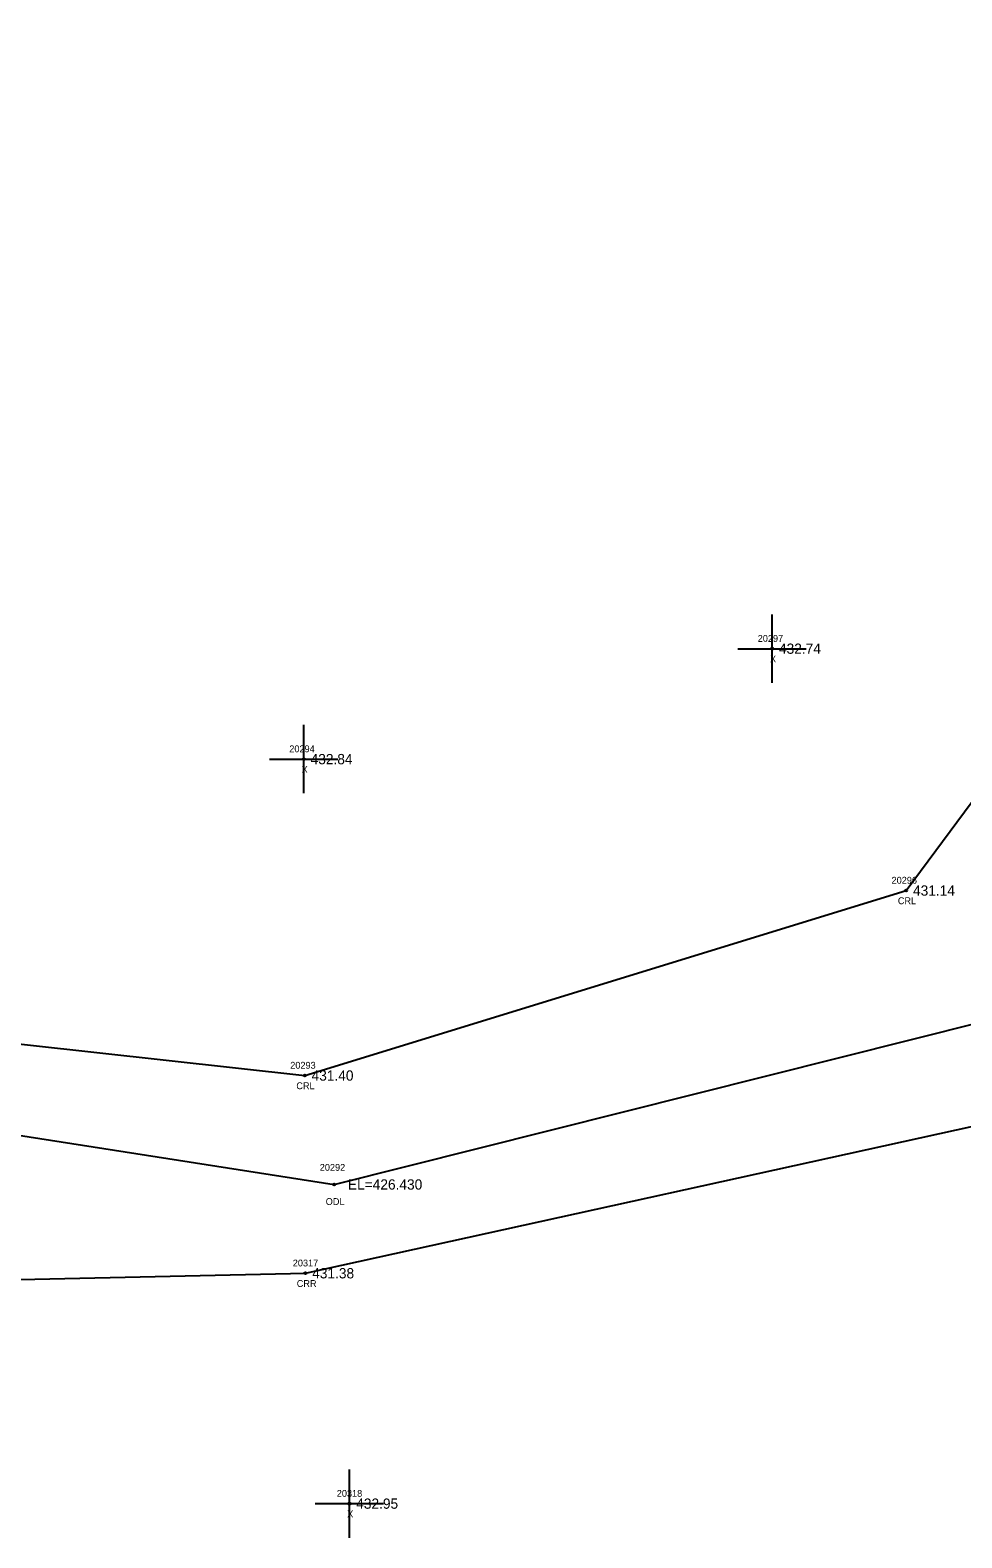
# Model space of a CAD drawing. Extents: x 1755707 to 1756750, y 975854 to 977363.
# Drawn here: x 1755843.1 to 1755979.4, y 976387.5 to 976608 of the extents above; entities that cross this region are included whole.
import ezdxf

# ---------------------------------------------------------------- set-up
doc = ezdxf.new("R2010")
doc.units = 0
for name, color, linetype in [('RD_EX_H2O', 7, 'Continuous'), ('RD_EX_H2O_txCode', 7, 'Continuous'), ('RD_EX_Misc', 7, 'Continuous'), ('RD_EX_Misc_txCode', 7, 'Continuous'), ('RD_EX_TX_H2O_ELEV', 7, 'Continuous'), ('RD_EX_TX_Misc_ELEV', 7, 'Continuous'), ('RD_SMD_Locator', 7, 'Continuous')]:
    doc.layers.add(name, color=color, linetype=linetype)

msp = doc.modelspace()

# ---------------------------------------------------------------- linework, layer by layer
at = {"layer": 'RD_EX_H2O'}
for points in [[(1755737.32, 976440.59), (1755791.96, 976465.24), (1755883.28, 976455.13), (1755971.27, 976482.19), (1756023.59, 976552.72), (1756109.16, 976576.08), (1756159.34, 976597.67), (1756188.28, 976619.95), (1756188.72, 976628.61)], [(1755742.06, 976428.66), (1755806.09, 976451.93), (1755887.6, 976439.2), (1755982.53, 976463.01), (1756033.69, 976542.66), (1756128.83, 976549.6), (1756169.54, 976582.49), (1756188.08, 976603.54), (1756206.03, 976613.84), (1756222.85, 976613.36), (1756242.15, 976615.93), (1756317.48, 976609.64), (1756394.89, 976590.11), (1756422.33, 976593.66), (1756518.23, 976582.93), (1756609.24, 976524.24), (1756704.51, 976490.62)], [(1755755.31, 976405), (1755806.36, 976424.52), (1755883.37, 976426.21), (1755989.26, 976449.51), (1756040.99, 976524.41), (1756109.22, 976532.55), (1756144.58, 976545.85), (1756166.57, 976563.07), (1756180.02, 976571), (1756216.66, 976584.76), (1756224.04, 976598.1), (1756313.82, 976585.45), (1756418.42, 976576.49), (1756511.71, 976558.86), (1756604.42, 976511.73), (1756702.67, 976481.09)]]:
    msp.add_lwpolyline(points, dxfattribs=at)
at = {"layer": 'RD_EX_Misc'}
for p, q in [((1755951.66, 976512.56), (1755951.66, 976522.56)), ((1755946.66, 976517.56), (1755956.66, 976517.56)), ((1755883.14, 976496.41), (1755883.14, 976506.41)), ((1755878.14, 976501.41), (1755888.14, 976501.41)), ((1755889.81, 976387.52), (1755889.81, 976397.52)), ((1755884.81, 976392.52), (1755894.81, 976392.52))]:
    msp.add_line(p, q, dxfattribs=at)
at = {"layer": 'RD_SMD_Locator'}
for centre in [(1755951.66, 976517.56), (1755883.14, 976501.41), (1755971.27, 976482.19), (1755883.28, 976455.13), (1755887.6, 976439.2), (1755883.37, 976426.21), (1755889.81, 976392.52)]:
    msp.add_circle(centre, 0.15, dxfattribs=at)

# ---------------------------------------------------------------- texts
at = {"layer": 'RD_EX_H2O_txCode'}
for s, p in [('20296', (1755969.13, 976483.19)), ('CRL', (1755970.05, 976480.19)), ('20293', (1755881.16, 976456.13)), ('CRL', (1755882.05, 976453.13)), ('20292', (1755885.48, 976441.2)), ('ODL', (1755886.35, 976436.2)), ('20317', (1755881.53, 976427.21)), ('CRR', (1755882.11, 976424.21))]:
    msp.add_text(s, height=1, dxfattribs=at).set_placement(p)
at = {"layer": 'RD_EX_Misc_txCode'}
for s, p in [('20297', (1755949.55, 976518.56)), ('X', (1755951.35, 976515.56)), ('20294', (1755881.02, 976502.41)), ('X', (1755882.82, 976499.41)), ('20318', (1755887.97, 976393.52)), ('X', (1755889.49, 976390.52))]:
    msp.add_text(s, height=1, dxfattribs=at).set_placement(p)
at = {"layer": 'RD_EX_TX_H2O_ELEV'}
for s, p in [('431.14', (1755972.27, 976481.44)), ('431.40', (1755884.28, 976454.38)), ('EL=426.430', (1755889.6, 976438.45)), ('431.38', (1755884.37, 976425.46))]:
    msp.add_text(s, height=1.5, dxfattribs=at).set_placement(p)
at = {"layer": 'RD_EX_TX_Misc_ELEV'}
for s, p in [('432.74', (1755952.66, 976516.81)), ('432.84', (1755884.14, 976500.66)), ('432.95', (1755890.81, 976391.77))]:
    msp.add_text(s, height=1.5, dxfattribs=at).set_placement(p)

doc.saveas('drawing.dxf')
